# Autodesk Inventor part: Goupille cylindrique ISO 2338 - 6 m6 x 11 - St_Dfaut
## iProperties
Created: 2007-07
Part Number: Goupille cylindrique ISO 2338 - 6 m6 x 11 - St_Dfaut
Document SubType Name: Modeling
Designer: EF
Density: 1 g/cm^3
Author: EF
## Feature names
1. Base1
